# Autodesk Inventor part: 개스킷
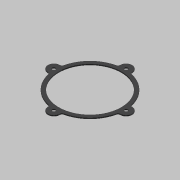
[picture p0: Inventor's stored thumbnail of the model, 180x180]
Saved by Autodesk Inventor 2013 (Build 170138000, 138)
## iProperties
Created: 2018-05
Part Number: 개스킷
Material: 고무, 실리콘
Document SubType Name: Modeling
Designer: mduedu
Density: 1.25 g/cm^3
Mass: 3.80534 g
Surface Area: 51.2947 cm^2
Volume: 3.04427 cm^3
Author: mduedu
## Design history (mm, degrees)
sketch "스케치1"
  geometry: C1 r 45 at (0, 0); C2 r 50 at (0, 0); 1 further point
  constraints: 2 centre point, 1 coincident, 1 concentric
  dimensions: "d12" = 90 diameter of C1; "d14" = 100 diameter of C2
extrude "돌출1" new body sketch "스케치1" distance "d10" = 1.5; taper "d11" = 0 deg
sketch "스케치2"
  geometry: C1 r 50 at (0, 0) reference; A1 r 8.5 centre (0, 52) between (8.074, 49.344) and (-8.074, 49.344); A2 r 50 centre (0, 0) between (-8.074, 49.344) and (8.074, 49.344); A3 r 8.5 centre (0, 52) between (-8.074, 49.344) and (8.074, 49.344); 1 further point
  constraints: 6 point on circle, 3 centre point, 1 concentric, 1 vertical alignment
  dimensions: "d15" = 52 distance of A1.centre point (0, 0); "d16" = 8.5 radius of A1; "d17" = 100 diameter of A2
extrude "돌출2" join sketch "스케치2" stored distance "d18" = 10; taper "d19" = 0 deg
sketch "스케치3"
  geometry: C1 r 2.5 at (0, 52); A1 r 8.5 centre (0, 52) between (8.074, 49.344) and (-8.074, 49.344) reference; 1 further point
  constraints: 1 centre point, 1 concentric
  dimensions: "d20" = 5 diameter of C1
extrude "돌출3" cut sketch "스케치3" stored distance "d21" = 10; taper "d22" = 0 deg
fillet "모깎기1" dims "d23" = 3
node "솔리드1"
pattern_circular "원형 패턴1" dims "d25" = 360 deg
